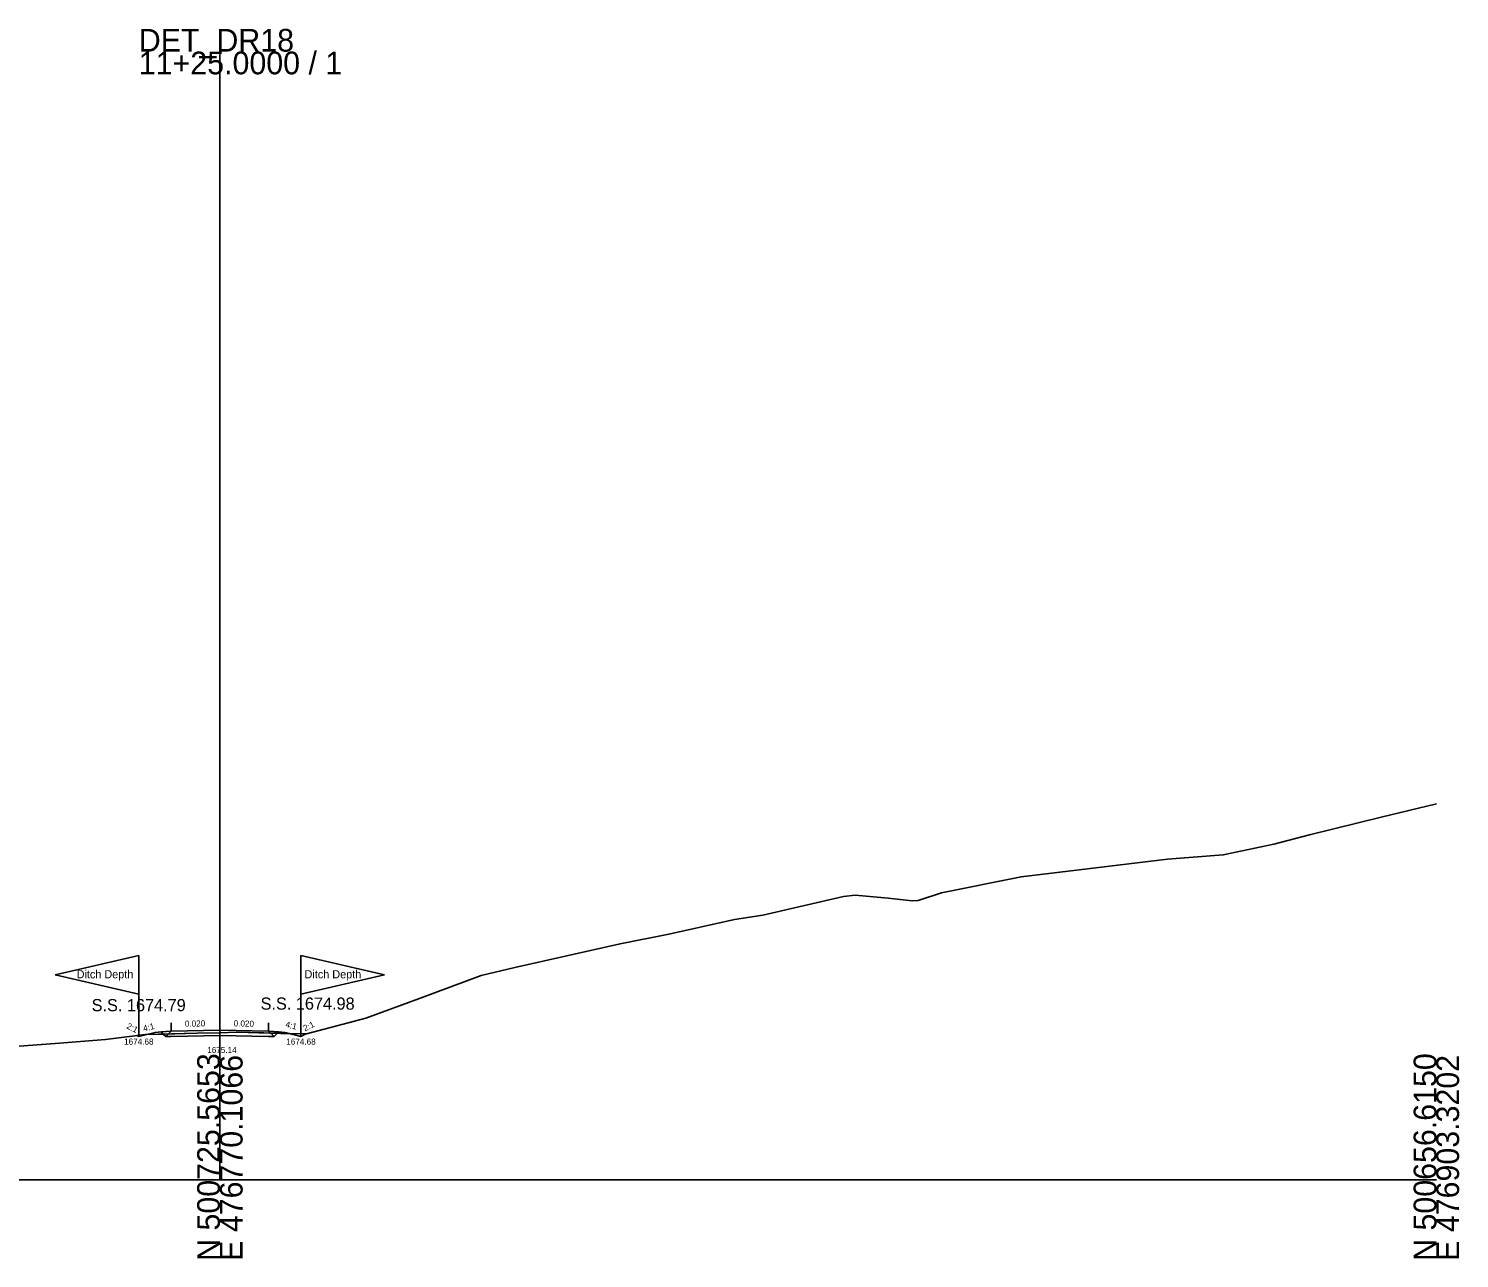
# Model space of a CAD drawing. Extents: x -26 to 303, y -10 to 3627.
# Drawn here: x 126.4 to 302.8, y 2490.3 to 2642 of the extents above; entities that cross this region are included whole.
import ezdxf

# ---------------------------------------------------------------- set-up
doc = ezdxf.new("R2010")
doc.units = 0
for name, color, linetype in [('Exist Cross Section Cell', 7, 'Continuous'), ('Exist XS Center Line Elevation Label', 7, 'Continuous'), ('Exist XS Ground Line', 7, 'Continuous'), ('Prop XS Ditch Slope Text', 7, 'Continuous'), ('Prop XS Ditch Standard Text', 7, 'Continuous'), ('Prop XS Dump Level', 7, 'Continuous'), ('Prop XS Earthwork Shape', 7, 'Continuous'), ('Prop XS EOT Tick Mark', 7, 'Continuous'), ('Prop XS Finish Grade', 7, 'Continuous'), ('Prop XS Finish Grade Earthwork', 7, 'Continuous'), ('Prop XS Finish Grade Pavement', 7, 'Continuous'), ('Prop XS Hydro Typical Ditch Data', 7, 'Continuous'), ('Prop XS Pvmt Edge Slope', 7, 'Continuous'), ('Prop XS SE Text', 7, 'Continuous'), ('Prop XS Shoulder Borrow Shape', 7, 'Continuous'), ('Prop XS Side Slope Text', 7, 'Continuous'), ('Prop XS SS Elevation Text', 7, 'Continuous'), ('Prop XS Subgrade Earthwork', 7, 'Continuous')]:
    doc.layers.add(name, color=color, linetype=linetype)

msp = doc.modelspace()

# ---------------------------------------------------------------- linework, layer by layer
at = {"layer": 'Exist Cross Section Cell'}
for p, q in [((150, 2500), (150, 2639.13)), ((0, 2500), (150, 2500)), ((150, 2500), (300, 2500))]:
    msp.add_line(p, q, dxfattribs=at)
at = {"layer": 'Exist XS Ground Line'}
msp.add_lwpolyline([(121.91, 2516.23), (130.23, 2516.84), (135.88, 2517.31), (140.84, 2517.92), (147.21, 2518.07), (150, 2518.14), (152.11, 2518.19), (157.5, 2518.06), (160.7, 2517.98), (167.99, 2519.92), (174.49, 2522.3), (182.2, 2525.21), (186.35, 2526.17), (199.36, 2529.09), (205.37, 2530.31), (213.46, 2532.11), (216.95, 2532.65), (226.91, 2534.94), (228.32, 2535.11), (232.41, 2534.72), (235.35, 2534.4), (236.11, 2534.43), (238.98, 2535.39), (248.8, 2537.38), (252.22, 2537.79), (266.86, 2539.54), (273.72, 2540.06), (279.98, 2541.39), (284.36, 2542.54), (293.18, 2544.71), (300, 2546.38)], dxfattribs=at)
at = {"layer": 'Prop XS Dump Level'}
for p, q in [((140, 2527.68), (129.7, 2525.28)), ((140, 2522.88), (140, 2527.68)), ((160, 2522.88), (160, 2527.68)), ((160, 2527.68), (170.3, 2525.28)), ((129.7, 2525.28), (140, 2522.88)), ((170.3, 2525.28), (160, 2522.88)), ((140, 2517.68), (140, 2522.88)), ((160, 2517.68), (160, 2522.88)), ((144, 2518.34), (150, 2518.46)), ((150, 2518.46), (156, 2518.34))]:
    msp.add_line(p, q, dxfattribs=at)
at = {"layer": 'Prop XS Earthwork Shape'}
for points in [[(139.77, 2517.79), (140.84, 2517.92), (140.99, 2517.92), (140, 2517.68)], [(143.01, 2517.97), (142.74, 2518.24), (142, 2518.18), (140.99, 2517.92)], [(144, 2517.67), (143.32, 2517.66), (143.01, 2517.97), (147.21, 2518.07), (150, 2518.14), (152.11, 2518.19), (157.1, 2518.07), (156.68, 2517.66), (156, 2517.67), (150, 2517.79)], [(157.1, 2518.07), (157.5, 2518.06), (158.58, 2518.03), (158, 2518.18), (157.26, 2518.24)], [(160, 2517.68), (160.6, 2517.98), (158.58, 2518.03)]]:
    msp.add_lwpolyline(points, close=True, dxfattribs=at)
at = {"layer": 'Prop XS EOT Tick Mark'}
for p, q in [((144, 2518.34), (144, 2519.34)), ((156, 2518.34), (156, 2519.34))]:
    msp.add_line(p, q, dxfattribs=at)
at = {"layer": 'Prop XS Finish Grade'}
for p, q in [((144, 2518.34), (142.74, 2518.24)), ((156, 2518.34), (157.26, 2518.24))]:
    msp.add_line(p, q, dxfattribs=at)
at = {"layer": 'Prop XS Finish Grade Earthwork'}
for p, q in [((140, 2517.68), (139.77, 2517.79)), ((142, 2518.18), (140, 2517.68)), ((142.74, 2518.24), (142, 2518.18)), ((157.26, 2518.24), (158, 2518.18)), ((158, 2518.18), (160, 2517.68)), ((160, 2517.68), (160.6, 2517.98))]:
    msp.add_line(p, q, dxfattribs=at)
at = {"layer": 'Prop XS Finish Grade Pavement'}
for p, q in [((144, 2518.34), (150, 2518.46)), ((150, 2518.46), (156, 2518.34))]:
    msp.add_line(p, q, dxfattribs=at)
at = {"layer": 'Prop XS Hydro Typical Ditch Data'}
for p, q in [((140, 2517.68), (139.77, 2517.79)), ((142, 2518.18), (140, 2517.68)), ((158, 2518.18), (160, 2517.68)), ((160, 2517.68), (160.6, 2517.98))]:
    msp.add_line(p, q, dxfattribs=at)
at = {"layer": 'Prop XS Pvmt Edge Slope'}
for p, q in [((144, 2518.34), (143.32, 2517.66)), ((156, 2518.34), (156.68, 2517.66))]:
    msp.add_line(p, q, dxfattribs=at)
at = {"layer": 'Prop XS Shoulder Borrow Shape'}
for points in [[(144, 2518.34), (143.32, 2517.66), (142.74, 2518.24)], [(144, 2518.34), (143.32, 2517.66), (142.74, 2518.24)], [(156.68, 2517.66), (157.26, 2518.24), (156, 2518.34)], [(156.68, 2517.66), (157.26, 2518.24), (156, 2518.34)]]:
    msp.add_lwpolyline(points, close=True, dxfattribs=at)
at = {"layer": 'Prop XS Subgrade Earthwork'}
for p, q in [((143.32, 2517.66), (142.74, 2518.24)), ((144, 2517.67), (143.32, 2517.66)), ((150, 2517.79), (144, 2517.67)), ((156, 2517.67), (150, 2517.79)), ((156, 2517.67), (156.68, 2517.66)), ((156.68, 2517.66), (157.26, 2518.24))]:
    msp.add_line(p, q, dxfattribs=at)

# ---------------------------------------------------------------- texts
at = {"layer": 'Exist Cross Section Cell'}
for s, p in [('DET_DR18', (140, 2639.13)), ('11+25.0000 / 1', (140, 2636.33))]:
    msp.add_text(s, height=2.8, dxfattribs=at).set_placement(p)
for s, p in [('N 500725.5653', (150, 2490)), ('E 476770.1066', (152.8, 2490)), ('N 500656.6150', (300, 2490)), ('E 476903.3202', (302.8, 2490))]:
    msp.add_text(s, height=2.8, rotation=90, dxfattribs=at).set_placement(p)
at = {"layer": 'Exist XS Center Line Elevation Label'}
msp.add_text('1675.14', height=0.75, dxfattribs=at).set_placement((148.44, 2515.63))
at = {"layer": 'Prop XS Ditch Slope Text'}
for rotation, p in [(345.9638, (158.03, 2518.84)), (14.0362, (140.64, 2518.28))]:
    msp.add_text('4:1', height=0.75, rotation=rotation, dxfattribs=at).set_placement(p)
at = {"layer": 'Prop XS Ditch Standard Text'}
for p in [(138.19, 2516.67), (158.19, 2516.67)]:
    msp.add_text('1674.68', height=0.75, dxfattribs=at).set_placement(p)
at = {"layer": 'Prop XS Dump Level'}
for s, height, p in [('Ditch Depth', 1, (132.34, 2524.85)), ('Ditch Depth', 1, (160.44, 2524.85)), ('Case1', 0.04, (142, 2518.14)), ('Case1', 0.04, (158, 2518.14))]:
    msp.add_text(s, height=height, dxfattribs=at).set_placement(p)
at = {"layer": 'Prop XS SE Text'}
for rotation, p in [(1.1458, (145.69, 2518.87)), (358.8542, (151.69, 2518.92))]:
    msp.add_text('0.020', height=0.75, rotation=rotation, dxfattribs=at).set_placement(p)
at = {"layer": 'Prop XS Side Slope Text'}
for rotation, p in [(26.5651, (160.5, 2518.29)), (333.4349, (138.42, 2518.71))]:
    msp.add_text('2:1', height=0.75, rotation=rotation, dxfattribs=at).set_placement(p)
at = {"layer": 'Prop XS SS Elevation Text'}
for s, p in [('S.S. 1674.79', (134.19, 2520.79)), ('S.S. 1674.98', (155.02, 2520.98))]:
    msp.add_text(s, height=1.5, dxfattribs=at).set_placement(p)

doc.saveas('drawing.dxf')
